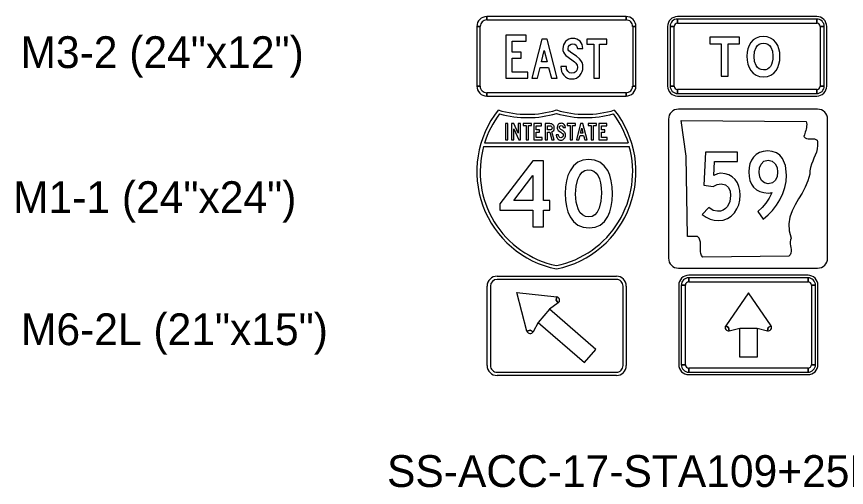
# Model space of a CAD drawing. Extents: x 620856.8 to 620948.6, y 415598.8 to 415658.2.
# Drawn here: x 620876.98 to 620887.41, y 415649.77 to 415655.69 of the extents above; entities that cross this region are included whole.
import ezdxf

# ---------------------------------------------------------------- set-up
doc = ezdxf.new("R2010")
doc.units = 0
doc.layers.add('SIGNS', color=7, linetype='Continuous')

msp = doc.modelspace()

# ---------------------------------------------------------------- linework, layer by layer
at = {"layer": 'SIGNS'}
for p, q in [((620882.889, 415655.647), (620882.889, 415655.689)), ((620884.639, 415655.689), (620884.639, 415655.647)), ((620887.037, 415655.689), (620885.287, 415655.689)), ((620885.287, 415655.605), (620885.287, 415655.657)), ((620887.037, 415655.657), (620887.037, 415655.605)), ((620882.764, 415655.564), (620882.806, 415655.564)), ((620884.723, 415655.564), (620884.764, 415655.564)), ((620885.162, 415655.564), (620885.162, 415654.814)), ((620885.194, 415655.564), (620885.246, 415655.564)), ((620887.079, 415655.564), (620887.131, 415655.564)), ((620887.162, 415654.814), (620887.162, 415655.564)), ((620882.806, 415654.814), (620882.764, 415654.814)), ((620882.889, 415654.689), (620882.889, 415654.73)), ((620884.639, 415654.73), (620884.639, 415654.689)), ((620884.764, 415654.814), (620884.723, 415654.814)), ((620885.246, 415654.814), (620885.194, 415654.814)), ((620885.287, 415654.72), (620885.287, 415654.772)), ((620887.037, 415654.772), (620887.037, 415654.72)), ((620887.131, 415654.814), (620887.079, 415654.814)), ((620885.287, 415654.689), (620887.037, 415654.689)), ((620887.048, 415654.524), (620885.298, 415654.524)), ((620883.153, 415654.342), (620883.124, 415654.342)), ((620883.124, 415654.342), (620883.124, 415654.138)), ((620883.153, 415654.138), (620883.153, 415654.342)), ((620883.227, 415654.342), (620883.199, 415654.342)), ((620883.199, 415654.342), (620883.199, 415654.138)), ((620883.283, 415654.221), (620883.227, 415654.342)), ((620883.314, 415654.342), (620883.283, 415654.342)), ((620883.283, 415654.342), (620883.283, 415654.221)), ((620883.314, 415654.138), (620883.314, 415654.342)), ((620883.45, 415654.342), (620883.345, 415654.342)), ((620883.345, 415654.342), (620883.345, 415654.317)), ((620883.345, 415654.317), (620883.382, 415654.317)), ((620883.382, 415654.317), (620883.382, 415654.138)), ((620883.412, 415654.138), (620883.412, 415654.317)), ((620883.412, 415654.317), (620883.45, 415654.317)), ((620883.45, 415654.317), (620883.45, 415654.342)), ((620883.577, 415654.342), (620883.48, 415654.342)), ((620883.48, 415654.342), (620883.48, 415654.138)), ((620883.51, 415654.262), (620883.51, 415654.314)), ((620883.51, 415654.314), (620883.577, 415654.314)), ((620883.577, 415654.314), (620883.577, 415654.342)), ((620883.776, 415654.313), (620883.773, 415654.294)), ((620883.788, 415654.331), (620883.776, 415654.313)), ((620883.796, 415654.338), (620883.788, 415654.331)), ((620883.805, 415654.342), (620883.796, 415654.338)), ((620883.801, 415654.294), (620883.803, 415654.304)), ((620883.803, 415654.304), (620883.808, 415654.311)), ((620883.815, 415654.345), (620883.805, 415654.342)), ((620883.808, 415654.311), (620883.816, 415654.316)), ((620883.825, 415654.346), (620883.815, 415654.345)), ((620883.816, 415654.316), (620883.826, 415654.318)), ((620883.836, 415654.345), (620883.825, 415654.346)), ((620883.826, 415654.318), (620883.836, 415654.316)), ((620883.846, 415654.343), (620883.836, 415654.345)), ((620883.836, 415654.316), (620883.843, 415654.312)), ((620883.843, 415654.312), (620883.847, 415654.305)), ((620883.855, 415654.338), (620883.846, 415654.343)), ((620883.847, 415654.305), (620883.85, 415654.294)), ((620883.863, 415654.332), (620883.855, 415654.338)), ((620883.874, 415654.315), (620883.863, 415654.332)), ((620883.879, 415654.294), (620883.874, 415654.315)), ((620884.004, 415654.342), (620883.899, 415654.342)), ((620883.899, 415654.342), (620883.899, 415654.317)), ((620883.899, 415654.317), (620883.936, 415654.317)), ((620883.936, 415654.317), (620883.936, 415654.138)), ((620883.966, 415654.138), (620883.966, 415654.317)), ((620883.966, 415654.317), (620884.004, 415654.317)), ((620884.004, 415654.317), (620884.004, 415654.342)), ((620884.268, 415654.342), (620884.163, 415654.342)), ((620884.163, 415654.342), (620884.163, 415654.317)), ((620884.163, 415654.317), (620884.201, 415654.317)), ((620884.201, 415654.317), (620884.201, 415654.138)), ((620884.23, 415654.138), (620884.23, 415654.317)), ((620884.23, 415654.317), (620884.268, 415654.317)), ((620884.268, 415654.317), (620884.268, 415654.342)), ((620884.396, 415654.342), (620884.299, 415654.342)), ((620884.299, 415654.342), (620884.299, 415654.138)), ((620884.329, 415654.262), (620884.329, 415654.314)), ((620884.329, 415654.314), (620884.396, 415654.314)), ((620884.396, 415654.314), (620884.396, 415654.342)), ((620885.173, 415654.399), (620885.173, 415652.649)), ((620887.173, 415652.649), (620887.173, 415654.399)), ((620883.227, 415654.138), (620883.227, 415654.276)), ((620883.227, 415654.276), (620883.291, 415654.138)), ((620883.553, 415654.262), (620883.51, 415654.262)), ((620883.51, 415654.166), (620883.51, 415654.234)), ((620883.51, 415654.234), (620883.553, 415654.234)), ((620883.553, 415654.234), (620883.553, 415654.262)), ((620883.792, 415654.199), (620883.763, 415654.199)), ((620883.763, 415654.199), (620883.763, 415654.198)), ((620883.763, 415654.198), (620883.764, 415654.185)), ((620883.773, 415654.294), (620883.774, 415654.283)), ((620883.774, 415654.283), (620883.777, 415654.274)), ((620883.777, 415654.274), (620883.781, 415654.265)), ((620883.781, 415654.265), (620883.788, 415654.257)), ((620883.788, 415654.257), (620883.821, 415654.234)), ((620883.793, 415654.186), (620883.792, 415654.199)), ((620883.802, 415654.288), (620883.801, 415654.294)), ((620883.806, 415654.282), (620883.802, 415654.288)), ((620883.821, 415654.27), (620883.806, 415654.282)), ((620883.845, 415654.254), (620883.821, 415654.27)), ((620883.821, 415654.234), (620883.834, 415654.224)), ((620883.834, 415654.224), (620883.841, 415654.217)), ((620883.841, 415654.217), (620883.848, 415654.207)), ((620883.86, 415654.24), (620883.845, 415654.254)), ((620883.848, 415654.207), (620883.851, 415654.196)), ((620883.851, 415654.196), (620883.849, 415654.184)), ((620883.85, 415654.294), (620883.879, 415654.294)), ((620883.868, 415654.23), (620883.86, 415654.24)), ((620883.874, 415654.22), (620883.868, 415654.23)), ((620883.878, 415654.208), (620883.874, 415654.22)), ((620883.879, 415654.196), (620883.878, 415654.208)), ((620883.878, 415654.184), (620883.879, 415654.196)), ((620884.371, 415654.262), (620884.329, 415654.262)), ((620884.329, 415654.166), (620884.329, 415654.234)), ((620884.329, 415654.234), (620884.371, 415654.234)), ((620884.371, 415654.234), (620884.371, 415654.262)), ((620884.668, 415654.096), (620882.861, 415654.096)), ((620883.124, 415654.138), (620883.153, 415654.138)), ((620883.199, 415654.138), (620883.227, 415654.138)), ((620883.291, 415654.138), (620883.314, 415654.138)), ((620883.382, 415654.138), (620883.412, 415654.138)), ((620883.48, 415654.138), (620883.585, 415654.138)), ((620883.585, 415654.166), (620883.51, 415654.166)), ((620883.585, 415654.138), (620883.585, 415654.166)), ((620883.764, 415654.185), (620883.767, 415654.174)), ((620883.767, 415654.174), (620883.772, 415654.163)), ((620883.772, 415654.163), (620883.779, 415654.153)), ((620883.779, 415654.153), (620883.788, 415654.145)), ((620883.788, 415654.145), (620883.798, 415654.139)), ((620883.799, 415654.175), (620883.793, 415654.186)), ((620883.798, 415654.139), (620883.809, 415654.135)), ((620883.809, 415654.167), (620883.799, 415654.175)), ((620883.821, 415654.164), (620883.809, 415654.167)), ((620883.809, 415654.135), (620883.821, 415654.134)), ((620883.833, 415654.166), (620883.821, 415654.164)), ((620883.821, 415654.134), (620883.833, 415654.135)), ((620883.843, 415654.174), (620883.833, 415654.166)), ((620883.833, 415654.135), (620883.845, 415654.139)), ((620883.849, 415654.184), (620883.843, 415654.174)), ((620883.845, 415654.139), (620883.854, 415654.145)), ((620883.854, 415654.145), (620883.863, 415654.153)), ((620883.863, 415654.153), (620883.87, 415654.162)), ((620883.87, 415654.162), (620883.875, 415654.173)), ((620883.875, 415654.173), (620883.878, 415654.184)), ((620883.936, 415654.138), (620883.966, 415654.138)), ((620884.201, 415654.138), (620884.23, 415654.138)), ((620884.299, 415654.138), (620884.404, 415654.138)), ((620884.404, 415654.166), (620884.329, 415654.166)), ((620884.404, 415654.138), (620884.404, 415654.166)), ((620885.173, 415652.649), (620885.173, 415652.649)), ((620883.018, 415652.423), (620884.518, 415652.423)), ((620884.518, 415652.423), (620884.518, 415652.423)), ((620885.298, 415652.524), (620887.048, 415652.524)), ((620886.927, 415652.434), (620885.427, 415652.434)), ((620884.518, 415652.381), (620883.018, 415652.381)), ((620885.427, 415652.35), (620885.427, 415652.402)), ((620886.927, 415652.402), (620886.927, 415652.35)), ((620882.893, 415651.298), (620882.893, 415652.298)), ((620882.935, 415652.298), (620882.935, 415651.298)), ((620884.602, 415651.298), (620884.602, 415652.298)), ((620884.643, 415652.298), (620884.643, 415651.298)), ((620885.302, 415652.309), (620885.302, 415651.309)), ((620885.333, 415652.309), (620885.386, 415652.309)), ((620886.969, 415652.309), (620887.021, 415652.309)), ((620887.052, 415651.309), (620887.052, 415652.309)), ((620883.762, 415652.12), (620883.768, 415652.161)), ((620883.786, 415652.086), (620883.762, 415652.12)), ((620885.927, 415651.777), (620885.892, 415651.8)), ((620886.462, 415651.8), (620886.427, 415651.777)), ((620883.394, 415651.731), (620883.434, 415651.743)), ((620883.434, 415651.743), (620883.471, 415651.723)), ((620885.937, 415651.737), (620885.927, 415651.777)), ((620886.427, 415651.777), (620886.418, 415651.737)), ((620885.386, 415651.309), (620885.333, 415651.309)), ((620887.021, 415651.309), (620886.969, 415651.309)), ((620883.018, 415651.214), (620884.518, 415651.214)), ((620884.518, 415651.173), (620883.018, 415651.173)), ((620883.018, 415651.173), (620883.018, 415651.173)), ((620885.427, 415651.215), (620885.427, 415651.267)), ((620885.427, 415651.184), (620886.927, 415651.184)), ((620886.927, 415651.267), (620886.927, 415651.215))]:
    msp.add_line(p, q, dxfattribs=at)
for points in [[(620884.639, 415655.689), (620882.889, 415655.689), (620882.889, 415655.647), (620884.639, 415655.647), (620884.639, 415655.689), (620884.639, 415655.689)], [(620887.037, 415655.657), (620885.287, 415655.657), (620885.287, 415655.605), (620887.037, 415655.605), (620887.037, 415655.657), (620887.037, 415655.657)], [(620882.764, 415655.564), (620882.764, 415654.814), (620882.806, 415654.814), (620882.806, 415655.564), (620882.764, 415655.564), (620882.764, 415655.564)], [(620884.764, 415654.814), (620884.764, 415655.564), (620884.723, 415655.564), (620884.723, 415654.814), (620884.764, 415654.814), (620884.764, 415654.814)], [(620885.194, 415655.564), (620885.194, 415654.814), (620885.246, 415654.814), (620885.246, 415655.564), (620885.194, 415655.564), (620885.194, 415655.564)], [(620887.131, 415654.814), (620887.131, 415655.564), (620887.079, 415655.564), (620887.079, 415654.814), (620887.131, 415654.814), (620887.131, 415654.814)], [(620883.405, 415654.988), (620883.207, 415654.988), (620883.207, 415655.167), (620883.32, 415655.167), (620883.32, 415655.242), (620883.207, 415655.242), (620883.207, 415655.379), (620883.385, 415655.379), (620883.385, 415655.453), (620883.128, 415655.453), (620883.128, 415654.914), (620883.405, 415654.914)], [(620883.821, 415655.061), (620883.821, 415655.057), (620883.823, 415655.027), (620883.83, 415654.999), (620883.842, 415654.974), (620883.859, 415654.951), (620883.88, 415654.93), (620883.904, 415654.916), (620883.93, 415654.907), (620883.96, 415654.904), (620883.989, 415654.907), (620884.015, 415654.915), (620884.039, 415654.929), (620884.06, 415654.949), (620884.076, 415654.972), (620884.088, 415654.997), (620884.095, 415655.024), (620884.098, 415655.054), (620884.095, 415655.082), (620884.087, 415655.109), (620884.073, 415655.135), (620884.054, 415655.159), (620884.017, 415655.191), (620883.96, 415655.23), (620883.922, 415655.258), (620883.914, 415655.272), (620883.911, 415655.289), (620883.916, 415655.311), (620883.929, 415655.329), (620883.948, 415655.342), (620883.971, 415655.346), (620883.995, 415655.342), (620884.013, 415655.33), (620884.022, 415655.313), (620884.029, 415655.289), (620884.098, 415655.289), (620884.087, 415655.339), (620884.061, 415655.378), (620884.041, 415655.394), (620884.02, 415655.405), (620883.995, 415655.411), (620883.969, 415655.414), (620883.944, 415655.411), (620883.921, 415655.404), (620883.899, 415655.392), (620883.88, 415655.376), (620883.852, 415655.335), (620883.843, 415655.287), (620883.845, 415655.262), (620883.852, 415655.24), (620883.864, 415655.219), (620883.881, 415655.2), (620883.96, 415655.143), (620883.99, 415655.12), (620884.008, 415655.104), (620884.024, 415655.079), (620884.03, 415655.053), (620884.025, 415655.024), (620884.011, 415654.999), (620883.988, 415654.981), (620883.96, 415654.975), (620883.93, 415654.982), (620883.906, 415655.002), (620883.893, 415655.029), (620883.889, 415655.061)], [(620884.235, 415654.914), (620884.306, 415654.914), (620884.306, 415655.342), (620884.398, 415655.342), (620884.398, 415655.404), (620884.146, 415655.404), (620884.146, 415655.342), (620884.235, 415655.342)], [(620885.835, 415654.939), (620885.922, 415654.939), (620885.922, 415655.347), (620886.065, 415655.347), (620886.065, 415655.429), (620885.694, 415655.429), (620885.694, 415655.347), (620885.835, 415655.347)], [(620882.889, 415654.689), (620884.639, 415654.689), (620884.639, 415654.73), (620882.889, 415654.73), (620882.889, 415654.689), (620882.889, 415654.689)], [(620885.287, 415654.72), (620887.037, 415654.72), (620887.037, 415654.772), (620885.287, 415654.772), (620885.287, 415654.72), (620885.287, 415654.72)], [(620886.903, 415654.37), (620886.908, 415654.351), (620886.91, 415654.331), (620886.909, 415654.312), (620886.907, 415654.293), (620886.903, 415654.274), (620886.898, 415654.255), (620886.892, 415654.236), (620886.886, 415654.218), (620886.881, 415654.199), (620886.876, 415654.181), (620886.89, 415654.165), (620886.908, 415654.156), (620886.927, 415654.152), (620886.949, 415654.151), (620886.97, 415654.152), (620886.991, 415654.152), (620887.01, 415654.15), (620887.026, 415654.144), (620887.04, 415654.132), (620887.048, 415654.112), (620887.048, 415654.066), (620887.043, 415654.024), (620887.032, 415653.983), (620887.017, 415653.945), (620887.002, 415653.906), (620886.986, 415653.869), (620886.971, 415653.83), (620886.959, 415653.79), (620886.95, 415653.749), (620886.948, 415653.705), (620886.926, 415653.623), (620886.892, 415653.544), (620886.852, 415653.469), (620886.808, 415653.394), (620886.764, 415653.319), (620886.727, 415653.243), (620886.699, 415653.165), (620886.684, 415653.082), (620886.688, 415652.995), (620886.713, 415652.901), (620886.706, 415652.878), (620886.703, 415652.854), (620886.704, 415652.83), (620886.707, 415652.806), (620886.71, 415652.782), (620886.713, 415652.759), (620886.713, 415652.736), (620886.71, 415652.714), (620886.702, 415652.693), (620886.686, 415652.673), (620885.603, 415652.663), (620885.588, 415652.683), (620885.58, 415652.707), (620885.576, 415652.733), (620885.576, 415652.761), (620885.576, 415652.791), (620885.577, 415652.82), (620885.575, 415652.849), (620885.569, 415652.876), (620885.558, 415652.901), (620885.539, 415652.921), (620885.413, 415652.921), (620885.395, 415653.933), (620885.332, 415654.38), (620886.903, 415654.37), (620886.903, 415654.37)], [(620885.598, 415653.198), (620885.646, 415653.165), (620885.696, 415653.142), (620885.748, 415653.128), (620885.803, 415653.123), (620885.862, 415653.129), (620885.915, 415653.147), (620885.962, 415653.178), (620886.003, 415653.221), (620886.034, 415653.268), (620886.056, 415653.321), (620886.069, 415653.379), (620886.073, 415653.442), (620886.07, 415653.499), (620886.058, 415653.551), (620886.039, 415653.597), (620886.011, 415653.638), (620885.975, 415653.672), (620885.933, 415653.697), (620885.884, 415653.712), (620885.829, 415653.717), (620885.788, 415653.711), (620885.744, 415653.691), (620885.753, 415653.866), (620886.04, 415653.866), (620886.04, 415653.982), (620885.64, 415653.982), (620885.619, 415653.566), (620885.736, 415653.551), (620885.785, 415653.577), (620885.837, 415653.585), (620885.889, 415653.574), (620885.927, 415653.539), (620885.947, 415653.493), (620885.954, 415653.436), (620885.944, 415653.361), (620885.914, 415653.3), (620885.889, 415653.273), (620885.861, 415653.254), (620885.827, 415653.242), (620885.79, 415653.239), (620885.733, 415653.25), (620885.679, 415653.286)], [(620886.927, 415652.402), (620885.427, 415652.402), (620885.427, 415652.35), (620886.927, 415652.35), (620886.927, 415652.402), (620886.927, 415652.402)], [(620883.268, 415652.218), (620883.768, 415652.161), (620883.762, 415652.12), (620883.786, 415652.086), (620883.678, 415652.007), (620883.534, 415651.842), (620883.471, 415651.723), (620883.434, 415651.743), (620883.394, 415651.731), (620883.268, 415652.218)], [(620885.333, 415652.309), (620885.333, 415651.309), (620885.386, 415651.309), (620885.386, 415652.309), (620885.333, 415652.309), (620885.333, 415652.309)], [(620886.177, 415652.215), (620885.892, 415651.8), (620885.927, 415651.777), (620885.937, 415651.737), (620886.068, 415651.767), (620886.287, 415651.767), (620886.418, 415651.737), (620886.427, 415651.777), (620886.462, 415651.8), (620886.177, 415652.215), (620886.177, 415652.215)], [(620887.021, 415651.309), (620887.021, 415652.309), (620886.969, 415652.309), (620886.969, 415651.309), (620887.021, 415651.309), (620887.021, 415651.309)], [(620884.116, 415651.336), (620884.259, 415651.501), (620883.678, 415652.007), (620883.534, 415651.842), (620884.116, 415651.336)], [(620886.287, 415651.402), (620886.068, 415651.402), (620886.068, 415651.767), (620886.287, 415651.767), (620886.287, 415651.402), (620886.287, 415651.402)], [(620885.427, 415651.215), (620886.927, 415651.215), (620886.927, 415651.267), (620885.427, 415651.267), (620885.427, 415651.215), (620885.427, 415651.215)]]:
    msp.add_lwpolyline(points, close=True, dxfattribs=at)
for points in [[(620883.456, 415654.914), (620883.527, 415654.914), (620883.56, 415655.049), (620883.666, 415655.049), (620883.701, 415654.914), (620883.772, 415654.914), (620883.649, 415655.404), (620883.579, 415655.404), (620883.456, 415654.914)], [(620886.574, 415655.188), (620886.571, 415655.238), (620886.562, 415655.283), (620886.546, 415655.324), (620886.524, 415655.361), (620886.492, 415655.395), (620886.455, 415655.419), (620886.413, 415655.434), (620886.364, 415655.439), (620886.316, 415655.434), (620886.274, 415655.419), (620886.238, 415655.395), (620886.208, 415655.361), (620886.186, 415655.325), (620886.171, 415655.285), (620886.162, 415655.239), (620886.159, 415655.19), (620886.162, 415655.139), (620886.171, 415655.092), (620886.187, 415655.05), (620886.208, 415655.012), (620886.239, 415654.976), (620886.276, 415654.95), (620886.319, 415654.934), (620886.368, 415654.929), (620886.416, 415654.934), (620886.459, 415654.95), (620886.496, 415654.975), (620886.527, 415655.011), (620886.547, 415655.048), (620886.562, 415655.09), (620886.571, 415655.137), (620886.574, 415655.188)], [(620886.485, 415655.194), (620886.483, 415655.153), (620886.478, 415655.117), (620886.469, 415655.086), (620886.456, 415655.061), (620886.44, 415655.042), (620886.419, 415655.028), (620886.396, 415655.02), (620886.368, 415655.017), (620886.338, 415655.021), (620886.312, 415655.031), (620886.29, 415655.049), (620886.273, 415655.074), (620886.254, 415655.124), (620886.248, 415655.188), (620886.254, 415655.249), (620886.273, 415655.299), (620886.291, 415655.323), (620886.313, 415655.34), (620886.338, 415655.351), (620886.368, 415655.354), (620886.397, 415655.351), (620886.421, 415655.341), (620886.442, 415655.324), (620886.46, 415655.302), (620886.479, 415655.253), (620886.485, 415655.194)], [(620883.577, 415655.118), (620883.612, 415655.261), (620883.649, 415655.118), (620883.577, 415655.118)], [(620883.034, 415654.513), (620883.034, 415654.513)], [(620884.495, 415654.513), (620884.495, 415654.513)], [(620885.298, 415654.524), (620885.298, 415654.524)], [(620887.048, 415654.524), (620887.048, 415654.524)], [(620883.049, 415654.465), (620883.049, 415654.465)], [(620883.764, 415654.471), (620883.764, 415654.471)], [(620884.479, 415654.465), (620884.479, 415654.465)], [(620883.654, 415654.138), (620883.654, 415654.235), (620883.681, 415654.235), (620883.708, 415654.138), (620883.737, 415654.138), (620883.707, 415654.239), (620883.72, 415654.246), (620883.73, 415654.257), (620883.735, 415654.27), (620883.737, 415654.285), (620883.736, 415654.297), (620883.734, 415654.308), (620883.729, 415654.318), (620883.723, 415654.326), (620883.715, 415654.333), (620883.706, 415654.338), (620883.695, 415654.341), (620883.683, 415654.342), (620883.622, 415654.342), (620883.622, 415654.138), (620883.654, 415654.138)], [(620883.654, 415654.262), (620883.654, 415654.314), (620883.684, 415654.314), (620883.694, 415654.313), (620883.703, 415654.307), (620883.708, 415654.299), (620883.71, 415654.288), (620883.708, 415654.277), (620883.704, 415654.269), (620883.696, 415654.264), (620883.685, 415654.262), (620883.654, 415654.262)], [(620884.047, 415654.138), (620884.061, 415654.194), (620884.105, 415654.194), (620884.12, 415654.138), (620884.149, 415654.138), (620884.098, 415654.342), (620884.069, 415654.342), (620884.018, 415654.138), (620884.047, 415654.138)], [(620885.173, 415654.399), (620885.173, 415654.399)], [(620884.068, 415654.223), (620884.083, 415654.283), (620884.098, 415654.223), (620884.068, 415654.223)], [(620882.848, 415654.055), (620883.391, 415654.055), (620883.918, 415654.055), (620884.68, 415654.055)], [(620886.294, 415653.235), (620886.363, 415653.14), (620886.425, 415653.193), (620886.481, 415653.251), (620886.53, 415653.315), (620886.574, 415653.385), (620886.61, 415653.461), (620886.636, 415653.538), (620886.652, 415653.616), (620886.657, 415653.695), (620886.644, 415653.814), (620886.607, 415653.905), (620886.572, 415653.946), (620886.529, 415653.975), (620886.478, 415653.992), (620886.42, 415653.998), (620886.365, 415653.993), (620886.317, 415653.979), (620886.276, 415653.955), (620886.241, 415653.921), (620886.215, 415653.882), (620886.196, 415653.838), (620886.185, 415653.789), (620886.182, 415653.735), (620886.185, 415653.677), (620886.197, 415653.626), (620886.216, 415653.582), (620886.243, 415653.544), (620886.279, 415653.511), (620886.322, 415653.488), (620886.371, 415653.474), (620886.428, 415653.469), (620886.452, 415653.471), (620886.475, 415653.472), (620886.473, 415653.472), (620886.439, 415653.403), (620886.398, 415653.341), (620886.35, 415653.285), (620886.294, 415653.235)], [(620884.168, 415653.892), (620884.096, 415653.883), (620884.033, 415653.856), (620883.98, 415653.812), (620883.937, 415653.75), (620883.909, 415653.689), (620883.89, 415653.621), (620883.878, 415653.546), (620883.875, 415653.464), (620883.878, 415653.379), (620883.89, 415653.301), (620883.909, 415653.232), (620883.937, 415653.171), (620883.981, 415653.109), (620884.035, 415653.064), (620884.1, 415653.038), (620884.176, 415653.029), (620884.25, 415653.038), (620884.314, 415653.065), (620884.367, 415653.11), (620884.41, 415653.173), (620884.436, 415653.232), (620884.454, 415653.3), (620884.465, 415653.376), (620884.469, 415653.459), (620884.465, 415653.546), (620884.454, 415653.623), (620884.435, 415653.692), (620884.409, 415653.751), (620884.366, 415653.813), (620884.311, 415653.857), (620884.245, 415653.883), (620884.168, 415653.892)], [(620886.545, 415653.731), (620886.538, 415653.675), (620886.517, 415653.63), (620886.48, 415653.597), (620886.428, 415653.585), (620886.378, 415653.596), (620886.341, 415653.628), (620886.32, 415653.672), (620886.314, 415653.727), (620886.319, 415653.785), (620886.337, 415653.832), (620886.373, 415653.87), (620886.424, 415653.883), (620886.475, 415653.871), (620886.515, 415653.835), (620886.537, 415653.788), (620886.545, 415653.731)], [(620883.469, 415653.045), (620883.602, 415653.045), (620883.602, 415653.254), (620883.681, 415653.254), (620883.681, 415653.375), (620883.602, 415653.375), (620883.602, 415653.876), (620883.469, 415653.876), (620883.053, 415653.333), (620883.053, 415653.254), (620883.469, 415653.254), (620883.469, 415653.045)], [(620883.469, 415653.375), (620883.23, 415653.375), (620883.469, 415653.688), (620883.469, 415653.375)], [(620884.33, 415653.468), (620884.323, 415653.365), (620884.301, 415653.279), (620884.278, 415653.23), (620884.248, 415653.195), (620884.213, 415653.175), (620884.171, 415653.168), (620884.128, 415653.174), (620884.091, 415653.194), (620884.06, 415653.226), (620884.036, 415653.271), (620884.012, 415653.356), (620884.005, 415653.456), (620884.012, 415653.556), (620884.034, 415653.645), (620884.057, 415653.695), (620884.086, 415653.731), (620884.12, 415653.753), (620884.161, 415653.76), (620884.2, 415653.756), (620884.235, 415653.742), (620884.264, 415653.719), (620884.288, 415653.687), (620884.306, 415653.646), (620884.32, 415653.596), (620884.328, 415653.536), (620884.33, 415653.468)], [(620883.764, 415652.555), (620883.764, 415652.555)], [(620883.018, 415652.423), (620883.018, 415652.423)], [(620883.764, 415652.513), (620883.764, 415652.513)], [(620885.298, 415652.524), (620885.298, 415652.524)], [(620887.048, 415652.524), (620887.048, 415652.524)], [(620882.893, 415652.298), (620882.893, 415652.298)], [(620884.643, 415651.298), (620884.643, 415651.298)], [(620884.518, 415651.173), (620884.518, 415651.173)]]:
    msp.add_lwpolyline(points, dxfattribs=at)
for centre, radius, start, end in [((620882.889, 415655.564), 0.125, 90.0002, 179.9998), ((620884.639, 415655.564), 0.125, 0, 90.0002), ((620885.287, 415655.564), 0.125, 90.0002, 179.9998), ((620885.287, 415655.564), 0.0937, 90.0002, 179.9998), ((620887.037, 415655.564), 0.125, 0, 90.0002), ((620887.037, 415655.564), 0.0937, 0, 90.0002), ((620882.889, 415655.564), 0.0833, 90.0002, 179.9998), ((620884.639, 415655.564), 0.0833, 0, 90.0002), ((620885.287, 415655.564), 0.0417, 90.0002, 179.9998), ((620887.037, 415655.564), 0.0417, 0, 90.0002), ((620882.889, 415654.814), 0.125, 179.9998, 270.0001), ((620882.889, 415654.814), 0.0833, 179.9998, 270.0001), ((620884.639, 415654.814), 0.125, 270.0001, 0.0003), ((620884.639, 415654.814), 0.0833, 270.0001, 0.0003), ((620885.287, 415654.814), 0.125, 179.9998, 270.0001), ((620885.287, 415654.814), 0.0937, 179.9998, 270.0001), ((620885.287, 415654.814), 0.0417, 179.9998, 270.0001), ((620887.037, 415654.814), 0.125, 270.0001, 0.0003), ((620887.037, 415654.814), 0.0937, 270.0001, 0.0003), ((620887.037, 415654.814), 0.0417, 270.0001, 0.0003), ((620884.014, 415653.738), 1.25, 141.669, 258.463), ((620883.399, 415655.709), 1.25, 253.009, 286.9909), ((620883.514, 415653.738), 1.25, 281.5371, 38.3311), ((620884.13, 415655.709), 1.25, 253.0091, 286.9911), ((620885.298, 415654.399), 0.125, 90.0002, 179.9998), ((620887.048, 415654.399), 0.125, 360, 90), ((620884.014, 415653.737), 1.208, 142.9959, 162.6952), ((620883.396, 415655.709), 1.292, 254.4391, 286.5746), ((620884.133, 415655.709), 1.292, 253.4255, 285.561), ((620883.515, 415653.737), 1.208, 17.3047, 37.0041), ((620884.014, 415653.737), 1.208, 164.7534, 258.0704), ((620883.515, 415653.737), 1.208, 281.9296, 15.2467), ((620885.298, 415652.649), 0.125, 180, 270), ((620887.048, 415652.649), 0.125, 270.0001, 0.0003), ((620883.515, 415653.737), 1.208, 281.9296126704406, 281.92963935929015), ((620884.014, 415653.737), 1.208, 258.0704, 258.0705), ((620883.018, 415652.298), 0.125, 90.0002, 179.9998), ((620884.518, 415652.298), 0.125, 0, 90), ((620885.427, 415652.309), 0.125, 90.0002, 179.9998), ((620886.927, 415652.309), 0.125, 360, 90.0002), ((620883.018, 415652.298), 0.0833, 90.0002, 179.9998), ((620884.518, 415652.298), 0.0833, 0, 90.0002), ((620885.427, 415652.309), 0.0937, 90.0002, 179.9998), ((620885.427, 415652.309), 0.0417, 90.0002, 179.9998), ((620886.927, 415652.309), 0.0937, 360, 90.0002), ((620886.927, 415652.309), 0.0417, 360, 90.0002), ((620883.762, 415652.12), 0.0417, 306.0496, 81.2756), ((620885.927, 415651.777), 0.0417, 147.7246, 282.9506), ((620886.427, 415651.777), 0.0417, 257.0495, 32.2756), ((620883.434, 415651.743), 0.0417, 196.7241, 331.9501), ((620883.018, 415651.298), 0.125, 179.9998, 270), ((620883.018, 415651.298), 0.0833, 179.9998, 270.0001), ((620884.518, 415651.298), 0.125, 270.0001, 360), ((620884.518, 415651.298), 0.0833, 270.0001, 0.0003), ((620885.427, 415651.309), 0.125, 179.9998, 270.0001), ((620885.427, 415651.309), 0.0937, 179.9998, 270.0001), ((620885.427, 415651.309), 0.0417, 179.9998, 270.0001), ((620886.927, 415651.309), 0.0937, 270.0001, 0.0003), ((620886.927, 415651.309), 0.0417, 270.0001, 0.0003), ((620886.927, 415651.309), 0.125, 270.0001, 0.0003)]:
    msp.add_arc(centre, radius, start, end, dxfattribs=at)

# ---------------------------------------------------------------- texts
for s, p in [('M3-2 (24"x12")', (620877.028, 415655.041)), ('M1-1 (24"x24")', (620876.935, 415653.217)), ('M6-2L (21"x15")', (620877.034, 415651.555)), ('SS-ACC-17-STA109+25EB', (620881.635, 415649.771))]:
    msp.add_text(s, height=0.4, rotation=0, dxfattribs=at).set_placement(p)

doc.saveas('drawing.dxf')
